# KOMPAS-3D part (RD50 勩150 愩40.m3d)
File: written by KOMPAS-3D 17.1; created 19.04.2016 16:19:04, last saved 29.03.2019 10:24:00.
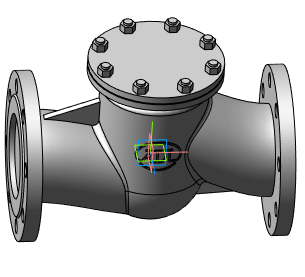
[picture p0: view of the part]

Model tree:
1. Операция без истории:2  (labels: Сталь 20  ГОСТ 1050-88)

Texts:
  RD50 Ду15 Ру40
  RD50 Ду20 Ру40
  RD50 Ду25 Ру40
  RD50 Ду32 Ру40
  RD50 Ду40 Ру40
  RD50 Ду50 Ру40
  RD50 Ду65 Ру40
  RD50 Ду80 Ру40
  RD50 Ду100 Ру40
  RD50 Ду125 Ру40
  RD50 Ду150 Ру40
  RD50 Ду200 Ру40
  RD50 Ду250 Ру40
  RD50 Ду300 Ру40
  RD50 Ду350 Ру40
  RD50 Ду400 Ру40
